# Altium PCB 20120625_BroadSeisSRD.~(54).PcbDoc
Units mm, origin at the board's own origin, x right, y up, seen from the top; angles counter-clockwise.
Board outline 68.5 x 51 mm, 4 copper layers (Top Layer, Mid-Layer 1, Mid-Layer 2, Bottom Layer); 59 components, 43 nets, 186 pads, 31 vias.
Unrouted connection lines stored in the file: 6.
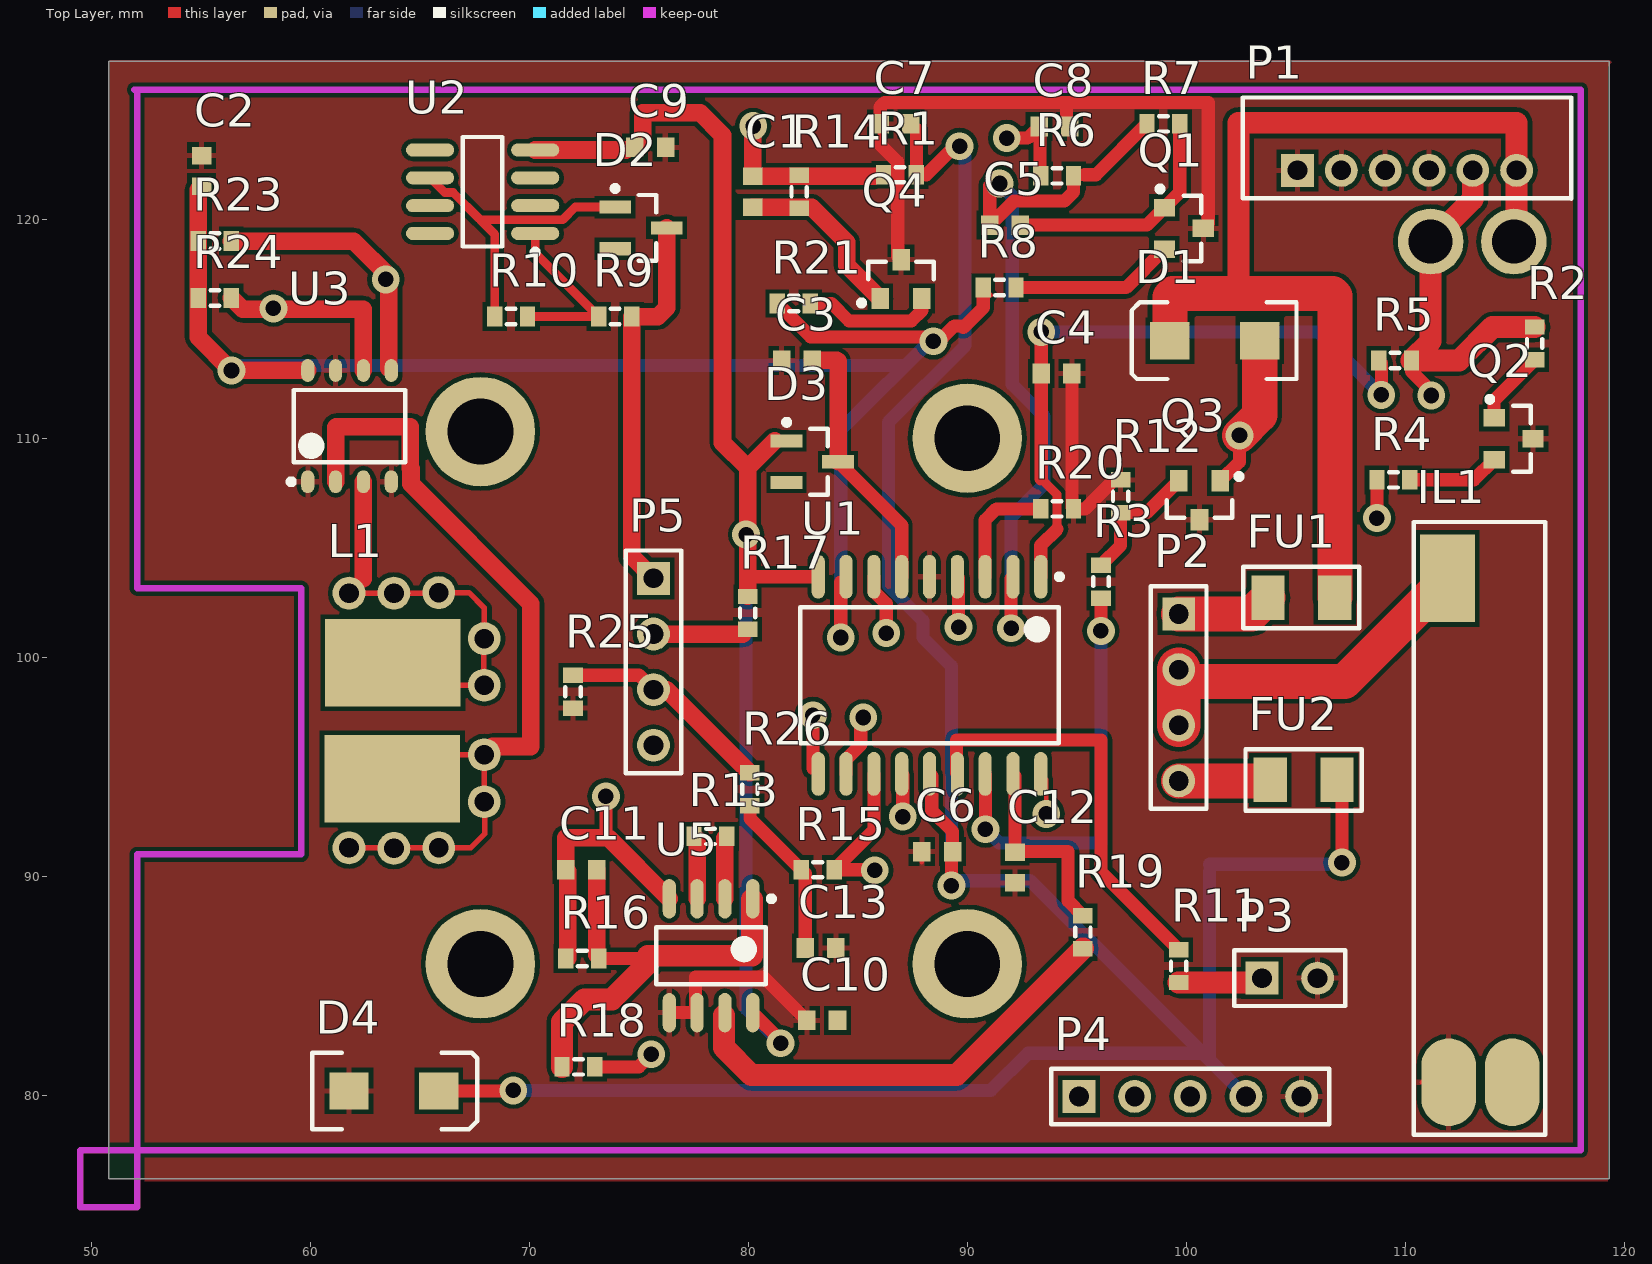
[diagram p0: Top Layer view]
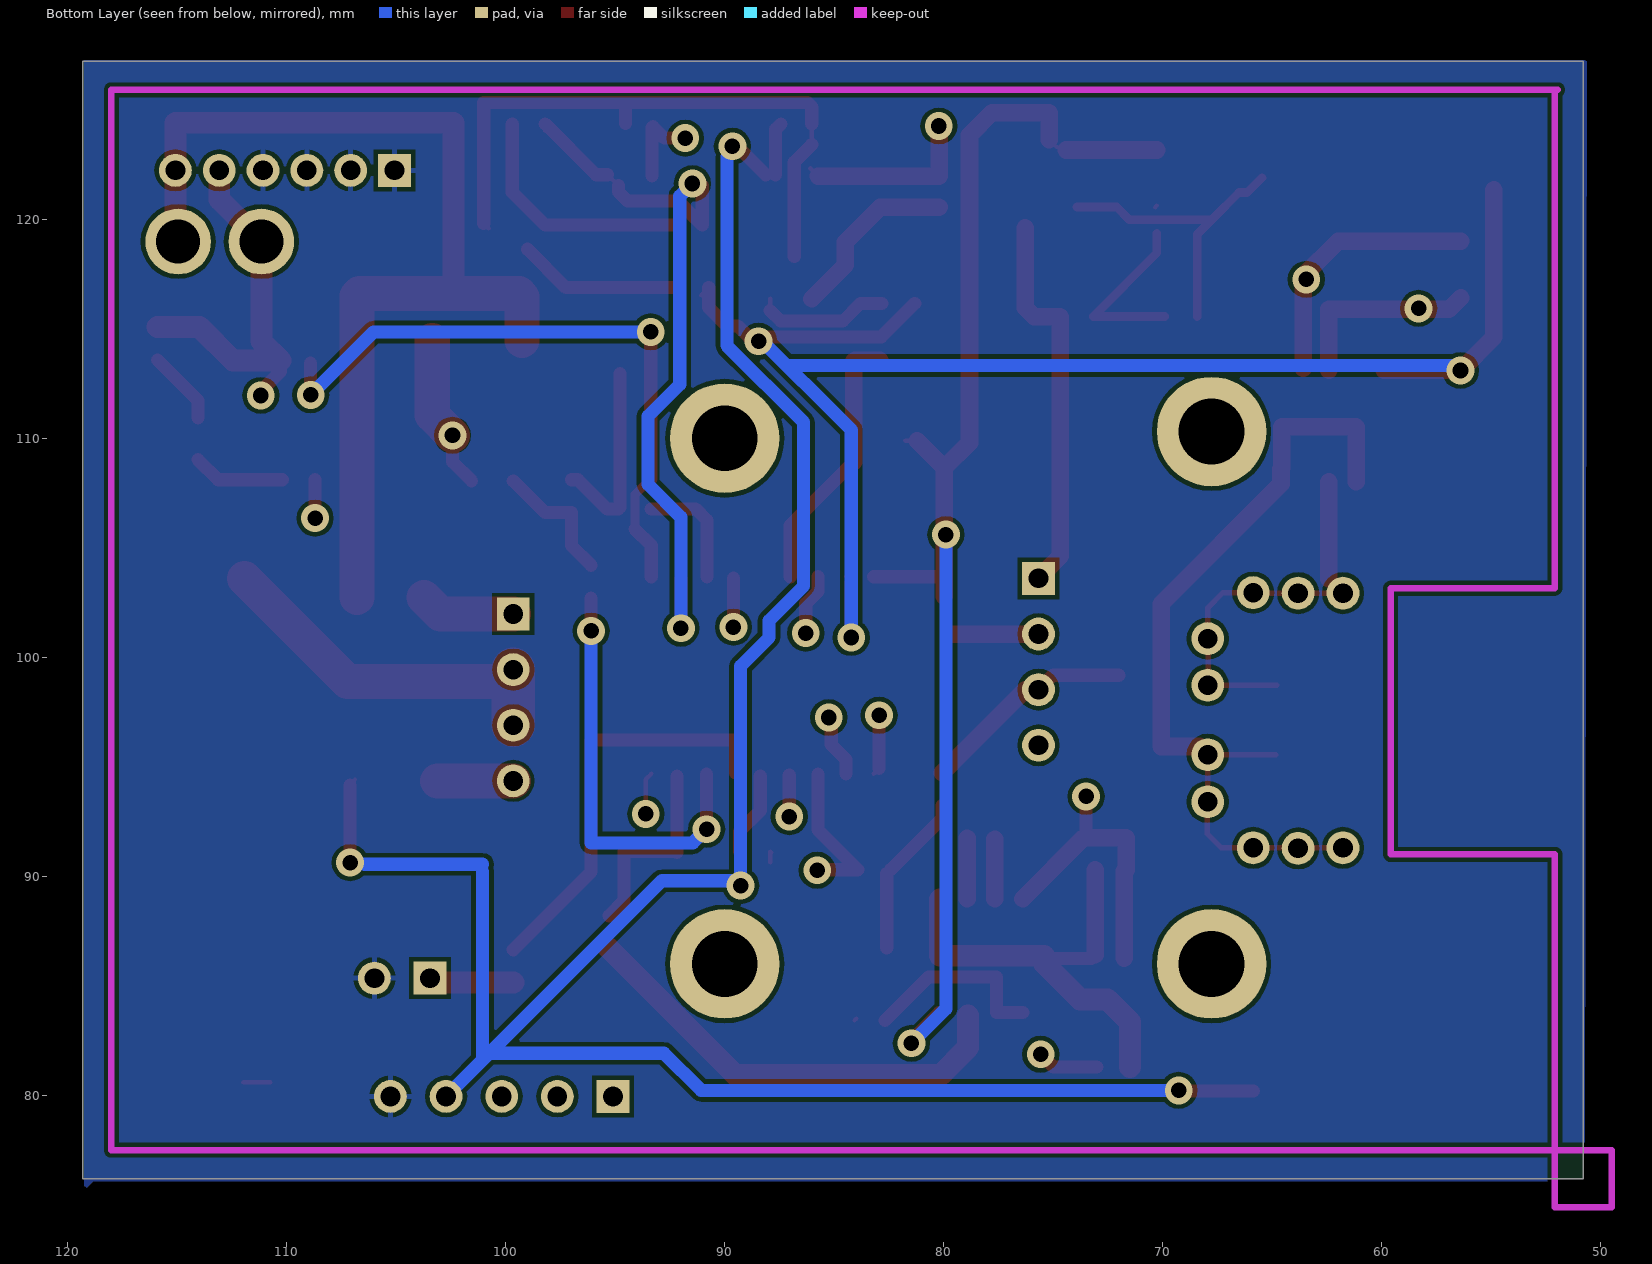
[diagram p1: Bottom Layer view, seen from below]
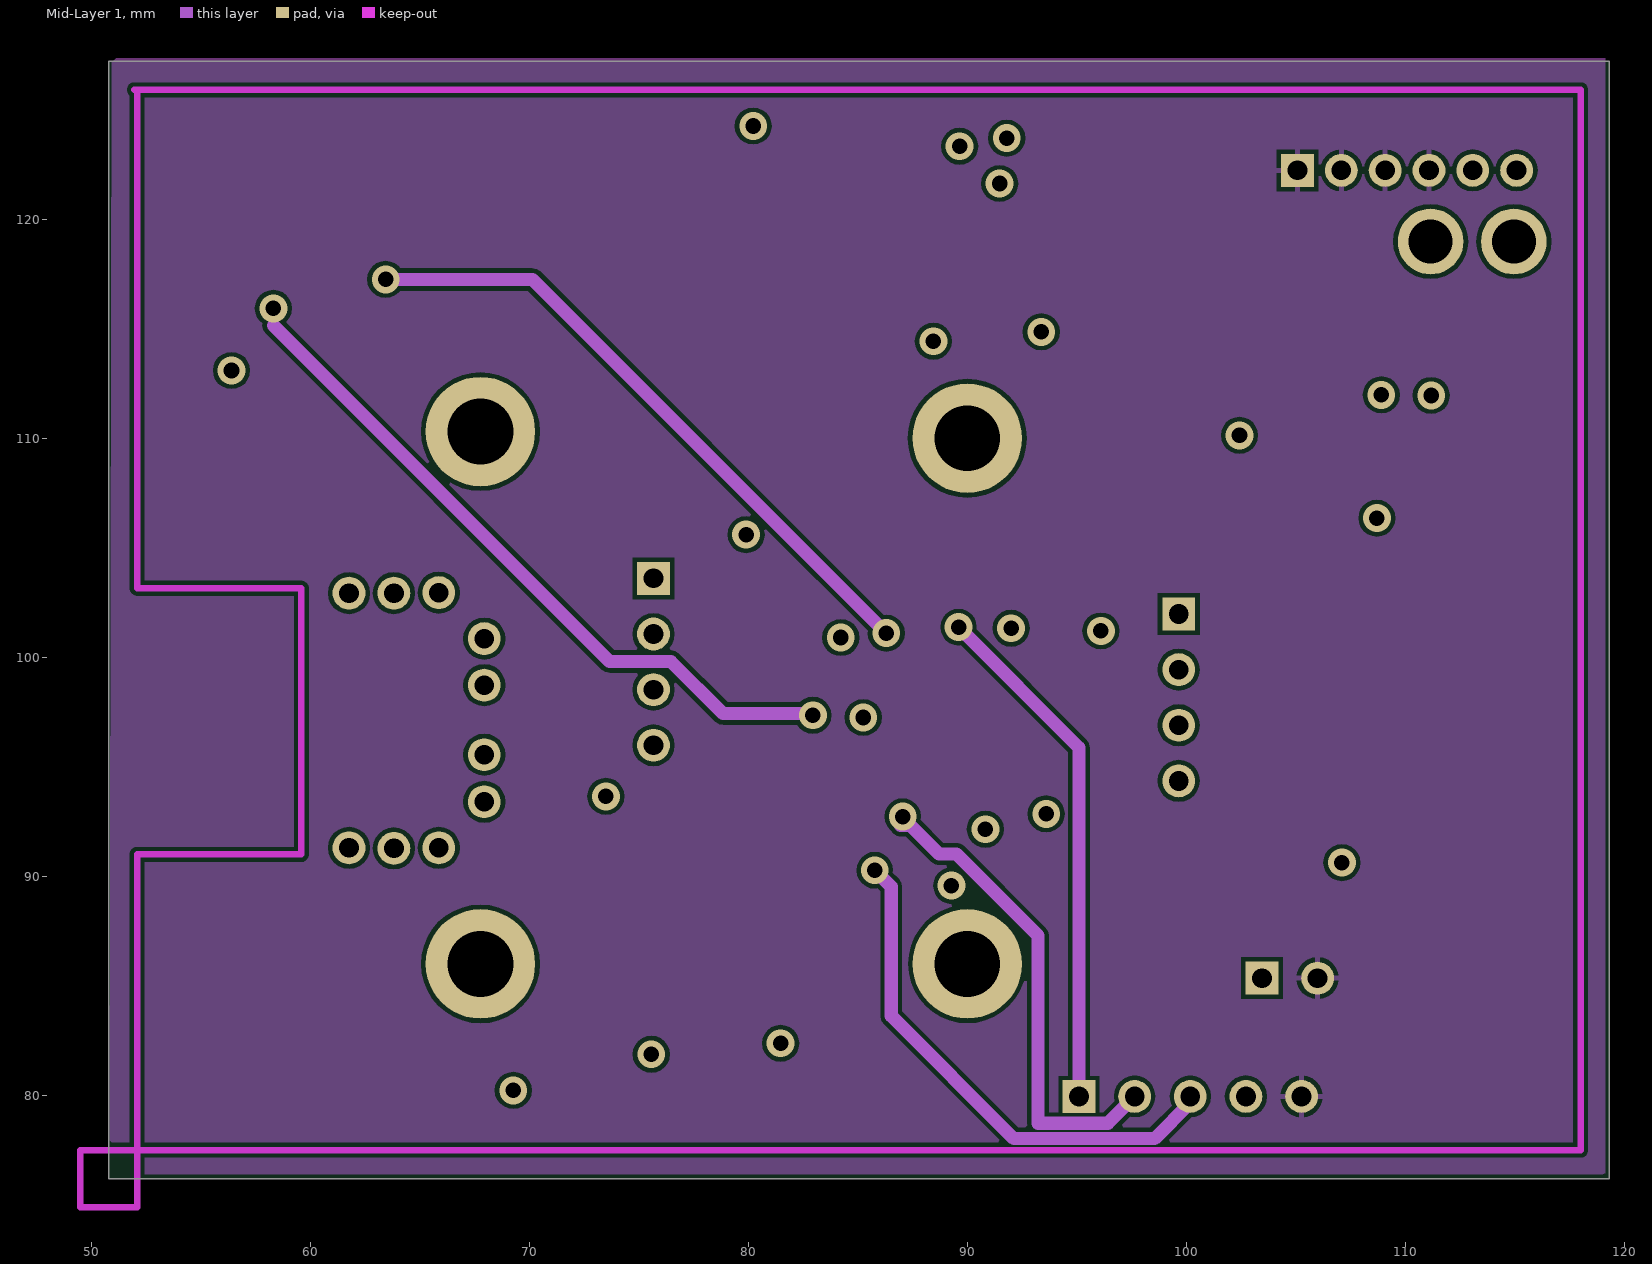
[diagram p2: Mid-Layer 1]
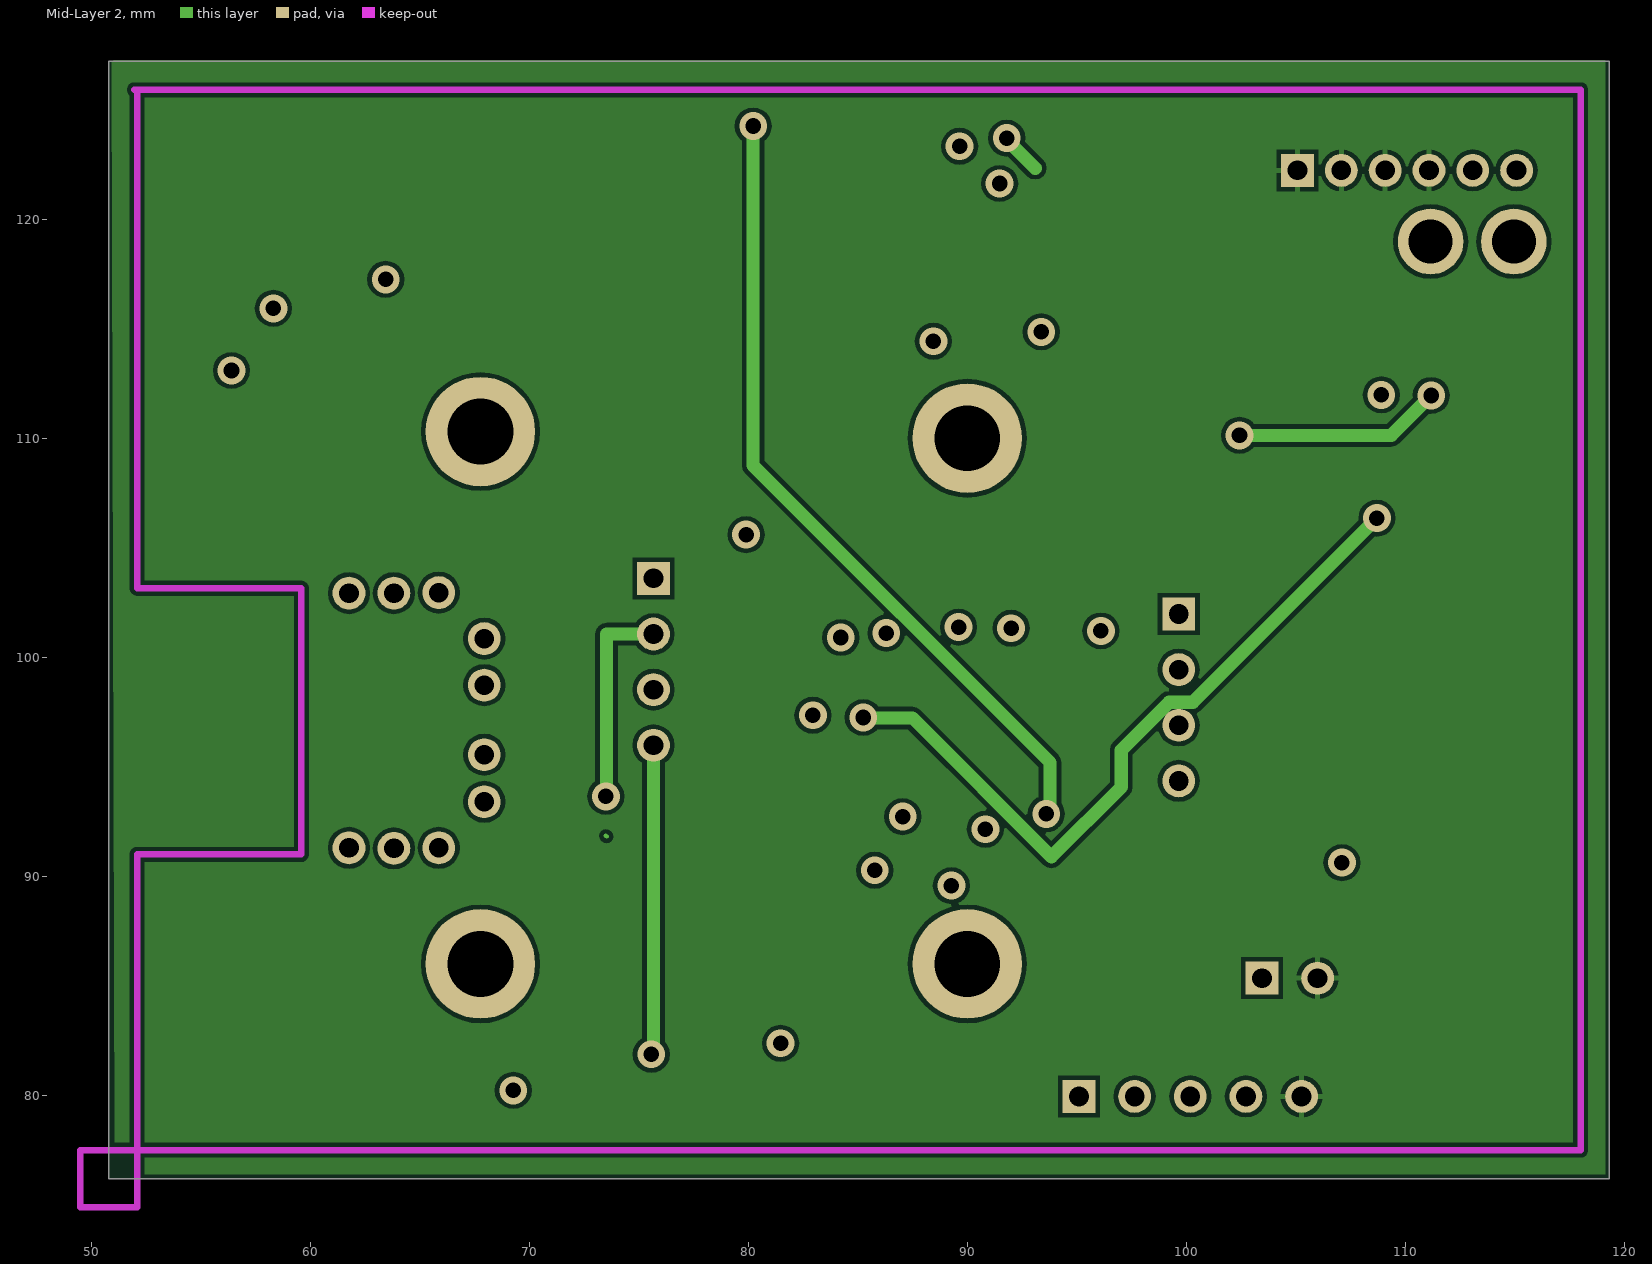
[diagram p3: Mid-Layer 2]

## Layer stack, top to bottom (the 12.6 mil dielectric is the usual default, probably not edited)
Top Layer: signal copper 0.0356
Dielectric: dielectric 0.32, FR-4, Dk 4.8
Mid-Layer 1: signal copper 0.0356
Dielectric: dielectric 0.32, FR-4, Dk 4.8
Mid-Layer 2: signal copper 0.0356
Dielectric: dielectric 0.32, FR-4, Dk 4.8
Bottom Layer: signal copper 0.0356

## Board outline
50.8,76.2 119.3,76.2 119.3,127.2 50.8,127.2

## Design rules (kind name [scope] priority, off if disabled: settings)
Clearance [All] p1: gap=0.2
PolygonConnect [All] p1: connectstyle=Relief reliefconductorwidth=0.254 reliefentries=4 polygonreliefangle="90 Angle"
RoomDefinition 2012_06_22_Sheet [InComponentClass('2012_06_22_Sheet')] p1: confinementstyle=ConfineIn formatcopy=TRUE lockcomponents=FALSE outline 124.968,76.183 450.469,76.183 450.469,107.298 124.968,107.298
RoutingVias [All] p1: holewidth=0.6 width=1 viastyle="Through Hole" minholewidth=0.711 minwidth=1.27 maxholewidth=0.711 maxwidth=1.27
SilkscreenOverComponentPads [All] p1: minsilkscreentomaskgap=0.254
SolderMaskExpansion [All] p1: expansion=0.102
Width [All] p1: maxlimit=0.2 minlimit=0.2 preferedwidth=0.2
27 further rules are at their usual default settings.

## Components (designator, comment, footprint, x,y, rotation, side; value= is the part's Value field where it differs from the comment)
C1 "Cap Semi" 1608[0603] 80.2,121.25 r90 top
C2 "Cap Semi" 1608[0603] 55.05,122.2 r270 top
C3 "Cap Semi" 1608[0603] 82.225,113.55 r0 top
C4 "Cap Semi" 1608[0603] 94.075,112.95 r180 top
C5 "Cap Semi" 1608[0603] 91.725,119.725 r180 top
C6 "Cap Semi" 1608[0603] 88.625,91.125 r0 top
C7 "Cap Semi" 1608[0603] 86.725,124.35 r0 top
C8 "Cap Semi" 1608[0603] 93.975,124.225 r180 top
C9 "Cap Semi" 1608[0603] 75.525,123.275 r180 top
C10 "Cap Semi" 1608[0603] 83.375,83.425 r0 top
C11 "Cap Semi" 1608[0603] 72.375,90.3 r180 top
C12 "Cap Semi" 1608[0603] 92.175,90.4 r90 top
C13 "Cap Semi" 1608[0603] 83.3,86.725 r180 top
D1 "RS1D" DiodeRS1D(recommendedfootprint) 101.3,114.45 r180 top
D2 "Diode BAS16" SOT-23_M 75.1,119.6 r0 top
D3 "Diode BAS16" SOT-23_M 82.925,108.925 r0 top
D4 "RS1D" DiodeRS1D(recommendedfootprint) 63.825,80.2 r0 top
FU1 "1A" FU(recommendedfootprint) 105.25,102.725 r0 top
FU2 "200mA" FU(recommendedfootprint) 105.35,94.4 r180 top
IL1 "ILS" ILS 114.875,103.6 r270 top
L1 "Inductor" INDC4532 63.775,97.1 r270 top
P1 "ConnectorToFB" "HIROSE DF3A-6P" 105.075,122.225 r0 top
P2 "Battery Pack pigtail" HDR1X4 99.65,101.975 r270 top
P3 "Connector to LED" HDR1X2 103.45,85.35 r0 top
P4 "Connector to Prog." HDR1X5 95.1,79.95 r0 top
P5 "Pressure Transducer pigtail" HDR1X4 75.675,103.6 r270 top
Q1 "NPN" transistor_SOT-23(recommendedfootprint) 99.975,119.575 r0 top
Q2 "NPN" transistor_SOT-23(recommendedfootprint) 115.025,109.975 r0 top
Q3 "MOSFET-IRLML" transistor_SOT-23(recommendedfootprint) 100.6,107.075 r270 top
Q4 "NPN" transistor_SOT-23(recommendedfootprint) 86.975,117.35 r90 top
R1 "Res3" J1-0603 86.925,122.025 r0 top
R2 "Res3" J1-0603 115.9,114.325 r90 top
R3 "Res3" J1-0603 96.1,103.45 r90 top
R4 "Res3" J1-0603 109.45,108.1 r0 top
R5 "Res3" J1-0603 109.525,113.55 r0 top
R6 "Res3" J1-0603 94.1,121.975 r180 top
R7 "Res3" J1-0603 98.95,124.35 r180 top
R8 "Res3" J1-0603 91.475,116.875 r0 top
R9 "Res3" J1-0603 73.925,115.55 r0 top
R10 "Res3" J1-0603 69.175,115.55 r180 top
R11 "Res3" J1-0603 99.65,85.9 r90 top
R12 "Res3" J1-0603 97,107.35 r270 top
R13 "Res3" J1-0603 78.275,91.825 r0 top
R14 "Res3" J1-0603 82.325,121.25 r90 top
R15 "Res3" J1-0603 83.175,90.3 r180 top
R16 "Res3" J1-0603 72.425,86.25 r180 top
R17 "Res3" J1-0603 79.975,102.025 r90 top
R18 "Res3" J1-0603 72.25,81.3 r180 top
R19 "Res3" J1-0603 95.275,87.45 r90 top
R20 "Res3" J1-0603 94.1,106.775 r180 top
R21 "Res3" J1-0603 82.075,116.15 r0 top
R23 "Res3" J1-0603 55.65,119 r0 top
R24 "Res3" J1-0603 55.65,116.4 r180 top
R25 "Res3" J1-0603 72,98.425 r90 top
R26 "Res3" J1-0603 80.075,93.975 r90 top
U1 "PIC16LF1827-I/SO" SOIC-SO18_L 88.275,99.175 r270 top
U2 "LM334D" SO8_N 67.875,121.25 r180 top
U3 "M24LR64" SO8N_N 61.8,110.55 r90 top
U5 "AD620BR" R-8D_N 78.3,86.375 r270 top

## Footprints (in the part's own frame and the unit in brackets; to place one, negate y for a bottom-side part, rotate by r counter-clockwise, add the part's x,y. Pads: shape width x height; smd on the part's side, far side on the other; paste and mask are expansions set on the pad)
1608[0603] [mm] "Chip Capacitor, Body 1.6x0.8mm, IPC High Density"
  rect 0.8x0.9 smd: 1(-0.7,0) 2(0.7,0)
  body extent -0.87,-0.48 0.87,0.48, height 1.3
DiodeRS1D(recommendedfootprint) [mm] "DO-214-AB/SMC; 2 C-Bend Leads; Body 7.9 x 5.9 mm, inc. leads (LxW)"
  rect 1.8x1.7 smd: 1(-2.05,0) 2(2.05,0)
  silkscreen extent -3.73,-1.75 3.8,1.75
FU(recommendedfootprint) [mm] "Thru-Hole; 2 Leads"
  rect 1.52x2.03 smd: 1(-1.525,0) 2(1.525,0)
  silkscreen extent -2.65,-1.4 2.65,1.4
HDR1X2 [mm] "Connector; Header; 2 Position"
  rect 1.5x1.5 hole 0.9: 1(0,0)
  round 1.5 hole 0.9: 2(2.54,0)
  silkscreen extent -1.27,-1.27 3.81,1.27
HDR1X4 [mm] "Connector; Header; 4 Position"
  rect 1.5x1.5 hole 0.9: 1(0,0)
  round 1.5 hole 0.9: 2(2.54,0) 3(5.08,0) 4(7.62,0)
  silkscreen extent -1.27,-1.27 8.89,1.27
HDR1X5 [mm] "Connector; Header; 5 Position"
  rect 1.5x1.5 hole 0.9: 1(0,0)
  round 1.5 hole 0.9: 2(2.54,0) 3(5.08,0) 4(7.62,0) 5(10.16,0)
  silkscreen extent -1.27,-1.27 11.43,1.27
"HIROSE DF3A-6P" [mm] "Connector; Header; 6 Position"
  rect 1.5x1.5 hole 0.9: 1(0,0)
  round 1.5 hole 0.9: 2(2,0) 3(4,0) 4(6,0) 5(8,0) 6(10,0)
  round 3 hole 2: 5(6.075,-3.25) 6(9.875,-3.25)
  Top Layer lines w0.254: 9.875,-3.25 10,-2.75
  Top Layer lines w1: 6.075,-3.25 8,-1.325 8,0 ; 10,-2.75 10,0
  silkscreen extent -2.5,-1.29 12.5,3.32
ILS [mm]
  rect 4x2.5 smd: 1(0,-2.95)
  oval 4x2.5 smd: 2(23,-2.9) 3(23,0)
  silkscreen extent -2.58,-4.5 25.4,1.5
INDC4532 [mm] "Chip Inductor, Body 4.5x3.2mm, IPC High Density"
  round 1.5 hole 0.9: 1(-5.85,2.1) 1(-5.825,0.05) 1(-5.825,-2) 1(-3.75,4.175) 1(-1.625,4.175) 2(1.55,4.175) 2(3.7,4.175) 2(5.8,2.1) 2(5.8,-2) 2(5.825,0.05)
  rect 4x6.2 smd: 1(-2.65,0) 2(2.65,-0.025)
  Top Layer lines w0.254: -5.825,-2 -5.825,0.05 -5.825,2.075 -5.85,2.1 -5.85,3.475 -5.15,4.175 -3.75,4.175 -3.725,4.15 ; 1.55,1.075 1.55,4.175 3.7,4.175 3.725,4.2 5.15,4.2 5.8,3.55 5.8,2.1 5.8,0.075 ; -1.625,4.175 -1.625,4.15 ; 5.8,0.05 5.8,-2 5.8,0.05 ; 5.8,0.05 5.8,0.075 ; 5.8,0.05 5.8,0.075 ; -1.625,1.068 -1.625,4.15 ; -1.625,1.068 -1.625,1.025 -1.625,1.068 ; -1.625,1.068 -1.625,4.15 ; -1.625,4.15 -3.725,4.15 ; -1.625,4.15 -3.725,4.15
J1-0603 [mm] "Chip Resistor, Body 1.6x0.8mm, IPC High Density"
  rect 0.7x0.9 smd: 1(-0.75,0) 2(0.75,0)
  silkscreen extent -0.2,-0.35 0.2,0.35, body extent -0.85,-0.48 0.85,0.48, height 0.9
R-8D_N [mm] "SOIC, 8-Leads, Body 4.9x3.9mm, Pitch 1.27mm, IPC Medium Density"
  oval 1.8x0.6 smd: 1(-2.6,1.905) 2(-2.6,0.635) 3(-2.6,-0.635) 4(-2.6,-1.905) 5(2.6,-1.905) 6(2.6,-0.635) 7(2.6,0.635) 8(2.6,1.905)
  silkscreen extent -2.72,-2.5 1.3,2.88, body extent -2,-2.5 2,2.5, height 2.59
SO8_N [mm] "SOIC, 8-Leads, Body 4.9x3.9mm, Pitch 1.27mm, IPC Medium Density"
  oval 2.2x0.6 smd: 1(-2.4,1.905) 2(-2.4,0.635) 3(-2.4,-0.635) 4(-2.4,-1.905) 5(2.4,-1.905) 6(2.4,-0.635) 7(2.4,0.635) 8(2.4,1.905)
  silkscreen extent -2.53,-2.5 0.9,2.88, body extent -1.95,-2.45 1.95,2.45, height 1.75
SO8N_N [mm] "SOP, 8-Leads, Body 5.3x5.3mm, Pitch 1.27mm, IPC Medium Density"
  oval 1.04x0.6 smd: 1(-2.54,1.905) 2(-2.54,0.635) 3(-2.54,-0.635) 4(-2.54,-1.905) 5(2.54,-1.905) 6(2.54,-0.635) 7(2.54,0.635) 8(2.54,1.905)
  silkscreen extent -2.66,-2.54 1.65,2.79, body extent -2.29,-2.54 2.29,2.54, height 2.13
SOIC-SO18_L [mm] "SOIC, 18-Leads, Body 11.5x7.5mm, Pitch 1.27mm, IPC High Density"
  oval 2x0.6 smd: 1(-4.5,5.08) 2(-4.5,3.81) 3(-4.5,2.54) 4(-4.5,1.27) 5(-4.5,0) 6(-4.5,-1.27) 7(-4.5,-2.54) 8(-4.5,-3.81) 9(-4.5,-5.08) 10(4.5,-5.08) 11(4.5,-3.81) 12(4.5,-2.54) 13(4.5,-1.27) 14(4.5,0) 15(4.5,1.27) 16(4.5,2.54) 17(4.5,3.81) 18(4.5,5.08)
  silkscreen extent -4.62,-5.9 3.1,6.06, body extent -3.8,-5.95 3.8,5.95, height 2.65
SOT-23_M [mm] "SOT23, 3-Leads, Body 2.9x1.3mm, Pitch 0.95mm, Lead Span 2.5mm, IPC Low Density"
  rect 1.45x0.6 smd: 1(-1.175,0.95) 2(-1.175,-0.95) 3(1.175,0)
  silkscreen extent -1.3,-1.5 0.7,1.92, body extent -0.7,-1.5 0.7,1.5, height 1.1
transistor_SOT-23(recommendedfootprint) [mm] "SOT23, 3-Leads, Body 2.9x1.3mm, Pitch 0.95mm, Lead Span 2.5mm, IPC Low Density"
  rect 0.972x0.802 smd: 1(-0.975,0.95) 2(-0.975,-0.95) 3(0.8,0)
  silkscreen extent -1.3,-1.5 0.7,1.92, body extent -0.7,-1.5 0.7,1.5, height 1.1

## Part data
C1 C2 C3 C4 C5 C6 C7 C8 C9 C10 C11 C12 C13: "Capacitor (Semiconductor SIM Model)"
D1 D4: library part Diode, "Default Diode"
D2 D3: "Silicon Switching Diode for High-Speed Switching"
FU1 FU2: library part "Fuse 1", "Fuse"
IL1: "SPDT Subminiature Toggle Switch, Right Angle Mounting, Vertical Actuation"
P1: "Header, 6-Pin"
P2 P5: "Header, 4-Pin"
P3: "Header, 2-Pin"
P4: "Header, 5-Pin"
Q1 Q2 Q4: "NPN Bipolar Transistor"
Q3: "N-Channel MOSFET"
R1 R2 R3 R4 R5 R6 R7 R8 R9 R10 R11 R12 R13 R14 R15 R16 R17 R18 R19 R20 R21 R23 R24 R25 R26: "Resistor"
U1: "EPROM-Based 8-Bit CMOS Microcontroller, 25 Bytes RAM, 4 MHz, 18-Pin SOIC, 3.0 to 5.5V Supply Range, Extended Temperature"
U2: "Three Terminal Adjustable Current Source"
U3: "32 Kbit Serial I²C Bus EEPROM"
U5: "Low-Cost, Low-Power Instrumentation Amplifier"

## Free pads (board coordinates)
  round 5 hole 3: 1(67.775,86) 1(67.775,110.3) 1(90,86) 1(90,110)

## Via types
v1: diameter 1.27, hole 0.711, Top Layer to Bottom Layer, 31 vias

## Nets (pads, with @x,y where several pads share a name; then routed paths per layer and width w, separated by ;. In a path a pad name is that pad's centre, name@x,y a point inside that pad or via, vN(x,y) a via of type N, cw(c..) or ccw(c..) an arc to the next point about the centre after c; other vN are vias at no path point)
ACTIVATION+: FU1.1 P2.1 | length 4.4
  Top Layer w1.6: P2.1 102.975,101.975 FU1.1
ANA_PRESSURE: C12.2 R19.2 U1.17 | length 9.3
  Top Layer w0.2: U1.17 U1.17@92.175,94.585 ; C12.2 C12.2@92.2,91.125
  Top Layer w0.6: C12.2 U1.17@92.175,94.585 ; C12.2@92.2,91.125 94.6,91.125 94.6,88.875 R19.2
B7: P4.2 U1.13 | length 23.8
  Top Layer w0.2: U1.13 U1.13@87.05,94.63
  Top Layer w0.6: v1(87.05,92.725) U1.13@87.05,94.63
  Mid-Layer 1 w0.6: v1@86.95,92.325 87.4,92.325 88.7,91.025 89.5,91.025 93.225,87.3 93.225,78.725 96.415,78.725 P4.2
CHECK-FIRE: R4.1 U1.11 | length 38
  Top Layer w0.2: v1@85.135,97.135 v1(85.25,97.25)
  Top Layer w0.6: U1.11 84.465,95.34 85.135,96.01 v1@85.135,97.135 ; v1(108.7,106.35) R4.1
  Mid-Layer 2 w0.6: v1@85.325,97.225 87.5,97.225 93.838,90.887 97.025,94.075 97.025,95.755 99.215,97.945 100.295,97.945 v1(108.7,106.35)
FB1: C8.2 D1.2 FU1.2 P1.6 R6.2 | length 52.1
  Top Layer w0.2: C8.2 C8.2@93.325,124.175 ; 99.25,116.45 99.4,116.6 ; 102.325,116.6 102.375,116.65 ; 106.675,116.6 106.775,116.5
  Top Layer w0.6: v1(91.8,123.7) 92.75,123.7 C8.2 ; R6.2@93.325,121.975 C8.2@93.325,124.175
  Top Layer w1: 102.375,116.65 102.375,124.4 115.075,124.4 P1.6@115.075,122.225
  Top Layer w1.6: D1.2 99.25,116.45 ; 99.4,116.6 102.325,116.6 106.675,116.6 ; FU1.2 106.775,116.5
  Mid-Layer 2 w0.6: v1@91.65,123.775 93.1,122.325
FB2: D1.1 P1.5 Q3.1 R2.2 R5.2 | length 30.5
  Top Layer w0.6: Q3.1 102.425,108.925 v1(102.425,110.125) ; R5.2 110.275,113.05 v1@111.175,112.15
  Top Layer w1: P1.5@111.15,118.975 111.15,114.425 R5.2 112.45,113.55 113.975,115.075 R2.2
  Top Layer w1.6: v1(102.425,110.125) 103.35,111.05 D1.1
  Mid-Layer 2 w0.6: v1(102.425,110.125) 109.35,110.125 v1(111.175,111.95)
FIRE: R3.1 U1.16 | length 19.2
  Top Layer w0.2: U1.16 U1.16@90.825,94.665
  Top Layer w0.6: v1(90.825,92.15) U1.16@90.825,94.665 ; v1(96.1,101.2) R3.1
  Bottom Layer w0.6: v1(90.825,92.15) 91.45,91.525 96.1,91.525 v1(96.1,101.2)
FLASH_LED: R11.2 U1.15 | length 19.2
  Top Layer w0.2: U1.15@89.5,94.72 U1.15
  Top Layer w0.6: U1.15@89.5,94.72 89.5,96.225 96.1,96.225 96.1,90.2 R11.2
GND: C2.1 C3.1 C4.1 C6.1 C7.1 C8.1 C9.1 C10.1 C12.1 C13.1 D4.1 IL1.2 P1.1 P1.2 P1.3 P1.4 P3.2 P4.5 Q1.3 Q2.3 Q3.3 Q4.3 R12.1 R20.1 R25.1 U1.5 U3.1 U3.4 U3.7 U5.5 U5.6 | length 49
  Top Layer w0.2: U5.6@77.6,83.775 77.6,83.84 U5.6 ; 84,83.5 84.075,83.425 ; 86.025,123.399 C7.1 ; C6.1@87.875,91.075 C6.1 87.925,90.65 ; C12.1@92.075,89.8 C12.1 ; C8.1@94.525,124.375 C8.1 ; R20.1@94.775,106.85 R20.1 ; Q1.3 Q1.3@101,119.8 ; IL1.2@110.74,80.6 IL1.2
  Top Layer w0.6: U5.5 U5.6@77.6,83.775 ; U5.6@77.6,83.84 77.6,85.4 80.7,85.4 C10.1 ; 86.025,123.399 86.825,122.599 Q4.3@86.825,118.3 ; C7.1 86.025,125.125 86.225,125.325 94.525,125.325 ; C8.1@94.525,124.375 94.525,125.325 ; R20.1@94.775,106.85 C4.1 ; R20.1 95.375,106.775 96.7,108.1 R12.1 ; Q1.3@101,119.8 101,125.325 94.525,125.325
IN+: D2.3 P4.3 P5.1 R9.2 R15.1 U1.12 | length 48.7
  Top Layer w0.2: v1@85.75,90.3 v1(85.775,90.275)
  Top Layer w0.6: U1.12 85.735,92.11 R15.1 v1@85.75,90.3
  Top Layer w0.8: P5.1 74.675,104.6 R9.2 75.875,115.55 76.275,115.95 D2.3
  Mid-Layer 1 w0.2: P4.3@100.18,79.655 P4.3
  Mid-Layer 1 w0.6: v1(85.775,90.275) 86.525,89.525 86.525,83.625 92.125,78.025 98.55,78.025 P4.3@100.18,79.655
IN-: P5.3 R25.2 R26.2 | length 9.3
  Top Layer w0.6: R25.2 75.02,99.175 P5.3
  Top Layer w0.8: P5.3@76.28,98.52 R26.2
LED+: P3.1 R11.1 | length 3.6
  Top Layer w1: R11.1 P3.1@103.25,85.15
LP0-VDD: C2.2 R8.1 R21.1 R23.1 R24.2 U1.8 U3.8 | length 74
  Top Layer w0.2: C2.2@54.9,121.35 C2.2 ; U1.8@84.225,103.435 U1.8 ; R8.1 R8.1@91.075,116.525
  Top Layer w0.6: R21.1 82.85,114.625 88.909,114.625 89.409,115.125 89.741,115.125 89.816,115.05 90.725,115.959 R8.1 ; v1(84.225,100.9) U1.8@84.225,103.435
  Top Layer w0.8: C2.2@54.9,121.35 R23.1 R24.2 54.9,114.6 v1(56.41,113.09) U3.8
  Bottom Layer w0.2: v1(56.41,113.09) v1@56.645,113.325
  Bottom Layer w0.6: v1@56.645,113.325 87.175,113.325 ; v1(84.225,100.9) 84.225,110.375 v1@88.575,114.725
  other v1: 88.45,114.425
LP1-VDD: C9.2 D3.1 R17.2 U1.9 U2.4 U5.8 | length 63.1
  Top Layer w0.2: C9.2 C9.2@75.175,123.625 ; 79.975,103.725 80.025,103.675 ; D3.1@81.2,109.875 D3.1 ; v1(81.475,82.375) v1@81.475,82.505
  Top Layer w0.6: 80.025,103.675 U1.9 ; U5.8 v1@81.475,82.505
  Top Layer w0.8: U2.4 74.405,123.155 ; C9.2@75.175,123.625 75.175,124.85 77.8,124.85 78.825,123.825 78.825,109.8 79.975,108.65 ; R17.2 79.975,103.725 79.975,108.65 ; D3.1@81.2,109.875 79.975,108.65
  Bottom Layer w0.2: v1(81.475,82.375) v1@81.7,82.15
  Bottom Layer w0.6: v1(79.9,105.6) 79.9,83.95 v1(81.475,82.375)
LP1_VDD: C10.2
MCLR/: P4.1 U1.4 | length 26
  Top Layer w0.2: U1.4 U1.4@89.6,103.62
  Top Layer w0.6: v1(89.6,101.375) U1.4@89.6,103.62
  Mid-Layer 1 w0.6: v1(89.6,101.375) 95.1,95.875 P4.1
NetC1_1: C1.1 Q4.1 R14.1 | length 8.2
  Top Layer w0.8: C1.1 82.9,120.55 84.5,118.95 84.5,117.9 Q4.1
NetC3_2: C3.2 D3.3 R20.2 U1.3 U1.6 | length 17.6
  Top Layer w0.2: 84.05,113.55 84.1,113.5
  Top Layer w0.6: D3.3 87.005,106.02 U1.6 ; U1.3 90.815,106.265 91.325,106.775 R20.2
  Top Layer w0.8: C3.2 84.05,113.55 ; D3.3 84.1,113.5
NetC5_1: C5.1 Q1.1 R7.1 | length 11
  Top Layer w0.6: C5.1 98.2,119.725 Q1.1 99.7,121.225 R7.1
NetC11_1: C11.1 R16.1 R18.2 U5.1 | length 20.8
  Top Layer w0.2: R16.1@73.075,86.425 73.25,86.25 R16.1 ; 75.3,86.25 75.425,86.375
  Top Layer w0.6: R16.1@73.25,86.25 75.3,86.25
  Top Layer w0.8: R16.1@73.075,86.425 C11.1
  Top Layer w1: R18.2 71.5,83.35 72.525,84.375 73.775,84.375 75.425,86.025 ; 75.425,86.375 80.175,86.375 U5.1@80.175,88.945
NetC13_2: C13.2 R15.2 R26.1 | length 7.5
  Top Layer w0.2: R15.2 R15.2@82.6,90.125
  Top Layer w0.6: R26.1 80.075,92.65 R15.2 ; C13.2 R15.2@82.6,90.125
NetD2_1: D2.1 R10.2 U2.6 | length 14.2
  Top Layer w0.2: 70.275,120.615 70.34,120.55
  Top Layer w0.4: U2.6 66.145,121.215 66.524,121.215 67.724,120.015 ; R10.2 68.425,119.314 67.764,119.975 71.525,119.975 72.1,120.55 D2.1
NetIL1_1: IL1.1 P2.2 P2.3 | length 17
  Top Layer w0.2: P2.2 100.185,98.9
  Top Layer w1.6: 100.185,98.9 107.225,98.9 IL1.1
  Top Layer w2: P2.3 P2.2
NetL1_1: L1.1 U3.3 | length 5.4
  Top Layer w0.2: L1.1@61.775,102.925 62.435,103.585
  Top Layer w0.8: 62.435,103.585 U3.3
NetL1_2: L1.2 U3.2 | length 25.1
  Top Layer w0.2: 61.165,110.49 61.2,110.525 ; L1.2@67.95,95.55 L1.2@68.325,95.925
  Top Layer w0.8: U3.2 61.165,110.49 ; 61.2,110.525 64.575,110.525 64.575,108.633 64.605,108.603 64.605,107.92 70.075,102.45 70.075,95.925 L1.2@68.325,95.925
NetQ1_2: Q1.2 R8.2 | length 7.5
  Top Layer w0.6: R8.2 97.25,116.875 Q1.2
NetQ2_1: Q2.1 R2.1 | length 3.4
  Top Layer w0.6: Q2.1 114.05,111.725 R2.1
NetQ2_2: Q2.2 R4.2 | length 4.2
  Top Layer w0.6: R4.2 113.125,108.1 Q2.2
NetQ3_2: Q3.2 R3.2 R12.2 | length 6
  Top Layer w0.6: R3.2 97,105.1 R12.2 98.2,106.6 Q3.2
NetQ4_2: Q4.2 R21.2 | length 6.2
  Top Layer w0.2: 87.925,115.825 Q4.2
  Top Layer w0.6: R21.2 83.8,116.15 84.6,115.35 87.45,115.35 87.925,115.825
NetR9_1: R9.1 R10.1 U2.1 | length 8.2
  Top Layer w0.4: R10.1 R9.1 70.275,118.45 U2.1
NetR13_1: R13.1 U5.3 | length 2.7
  Top Layer w0.8: U5.3 R13.1@77.665,91.685
NetR13_2: R13.2 U5.2 | length 2.8
  Top Layer w0.8: U5.2 R13.2@78.935,91.735
NetR19_1: R19.1 U5.7 | length 20.8
  Top Layer w1: U5.7@78.891,83.641 78.891,82.184 80.15,80.925 89.5,80.925 R19.1
OUT+: C11.2 P5.2 R16.2 R17.1 U5.4 | length 27
  Top Layer w0.2: C11.2 C11.2@71.75,90.225 ; 73.5,91.87 73.62,91.75
  Top Layer w0.6: 73.5,91.87 v1(73.5,93.65)
  Top Layer w0.8: C11.2 71.675,91.75 73.62,91.75 U5.4 ; R16.2@71.75,86.25 C11.2@71.75,90.225 ; P5.2 R17.1@79.76,101.06
  Mid-Layer 2 w0.2: 73.5,91.85 73.535,91.815 ; v1(73.5,93.65) v1@73.535,93.685
  Mid-Layer 2 w0.6: v1@73.535,93.685 73.535,101.06 P5.2
OUT-: P5.4 R18.1 | length 18
  Top Layer w0.2: v1(75.575,81.875) 75.875,81.875 v1@75.725,82.025
  Top Layer w0.6: R18.1 75,81.3 v1@75.725,82.025
  Mid-Layer 2 w0.2: v1(75.575,81.875) 75.875,81.875 v1@75.675,82.075
  Mid-Layer 2 w0.6: v1@75.675,82.075 P5.4
PCB+: FU2.2 P2.4 | length 3.5
  Top Layer w1.6: P2.4 FU2.2@103.12,94.355
SCLK: R24.1 U1.10 U3.6 | length 44.8
  Top Layer w0.2: U1.10@82.95,94.92 U1.10
  Top Layer w0.6: U1.10@82.95,94.92 v1(82.95,97.35)
  Top Layer w0.8: R24.1 56.915,115.885 62.435,115.885 U3.6
  Mid-Layer 1 w0.2: 58.325,115.15 v1(58.325,115.925)
  Mid-Layer 1 w0.6: 58.325,115.15 73.675,99.8 76.475,99.8 78.85,97.425 v1@83.15,97.425
SDA: R23.2 U1.7 U3.5 | length 44.1
  Top Layer w0.6: U1.7 85.735,103.015 86.3,102.45 v1(86.3,101.1)
  Top Layer w0.8: R23.2 62,119 63.6,117.4 U3.5@63.6,113.195
  Mid-Layer 1 w0.6: v1(63.45,117.25) 70.15,117.25 v1@86.05,101.35
VBAT1: C1.2 R1.1 R14.2 U1.18 | length 47.4
  Top Layer w0.2: 85.725,121.95 R1.1@86.1,122.325 ; U1.18 93.6,94.43 v1(93.6,92.85)
  Top Layer w0.8: v1@80.2,124.025 C1.2 85.725,121.95
  Mid-Layer 2 w0.6: v1(80.225,124.25) 80.225,108.75 93.775,95.2 v1@93.775,92.55
VBAT2: C5.2 R6.1 R7.2 U1.2 | length 36.2
  Top Layer w0.2: v1@91.025,121.525 90.95,121.6 90.975,121.625 v1(91.475,121.625) ; U1.2@92,103.59 U1.2 ; 94.85,121.525 95.35,122.025 ; R7.2@98.2,124.025 R7.2
  Top Layer w0.6: v1@91.025,121.525 C5.2 92.125,120.825 94.425,120.825 94.85,121.25 94.85,121.525 ; v1(92,101.325) U1.2@92,103.59 ; 95.35,122.025 95.875,122.025 R7.2
  Bottom Layer w0.6: v1(91.475,121.625) 92.05,121.05 92.05,112.45 93.5,111 93.5,107.9 92,106.4 v1(92,101.325)
VDD: C6.2 C7.2 D4.2 FU2.1 P4.4 R1.2 U1.14 | length 121.1
  Top Layer w0.2: v1@69.25,80.2 v1(69.275,80.225) ; R1.2 88.125,122.025 ; U1.14 U1.14@88.375,94.575 ; C6.2@89.275,91.075 C6.2 ; v1@89.425,123.325 v1(89.65,123.325) ; FU2.1 FU2.1@107.1,94.175
  Top Layer w0.6: D4.2 v1@69.25,80.2 ; C7.2 87.675,124.1 R1.2 ; 88.125,122.025 v1@89.425,123.325 ; U1.14@88.375,94.575 88.375,93 89.325,92.05 C6.2 ; v1(89.275,89.575) C6.2@89.275,91.075 ; v1(107.1,90.625) FU2.1@107.1,94.175
  Bottom Layer w0.2: v1(89.275,89.575) v1@89.275,89.8 ; v1(89.65,123.325) 89.425,123.325 v1@89.9,122.85 ; 100.745,81.925 P4.4
  Bottom Layer w0.6: v1(69.275,80.225) 91.075,80.225 92.775,81.925 100.745,81.925 ; v1@89.9,122.85 89.9,114.225 86.4,110.725 86.4,103.253 87.975,101.678 87.975,100.9 89.275,99.6 89.275,89.8 92.87,89.8 P4.4 ; 101.05,81.62 101.05,90.225 ; 101.05,90.55 106.45,90.55
VFIRE: C4.2 R5.1 U1.1 | length 30.1
  Top Layer w0.2: R5.1 R5.1@108.9,113.425
  Top Layer w0.4: 93.375,108.15 94.1,107.425 94.1,105.85
  Top Layer w0.6: U1.1 93.355,105.105 94.1,105.85 ; 93.375,108.15 C4.2 v1(93.375,114.85) ; v1(108.9,111.975) R5.1@108.9,113.425
  Bottom Layer w0.6: v1(93.375,114.85) 106.025,114.85 v1(108.9,111.975)
pads on no net: D2.2 D3.2 IL1.3 U2.2 U2.3 U2.5 U2.7 U2.8

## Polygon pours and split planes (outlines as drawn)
GND on Top Layer "Top Layer-No Net" (solid, pour order 4): 50.85,127.25 119.325,127.25 119.425,127.15 119.225,126.95 119.225,76.075 51.05,76.075 50.85,76.275
GND on Mid-Layer 1 "Top Layer-No Net" (solid, pour order 6): 50.95,127.15 51.15,127.35 119.125,127.35 119.125,76.275 119.225,76.175 119,76.4 50.85,76.4
GND on Mid-Layer 2 "Top Layer-No Net" (solid, pour order 8): 50.95,127.25 119.125,127.25 119.125,76.4 51.275,76.4 51.075,76.6
GND on Bottom Layer "Top Layer-No Net" (solid, pour order 10): 50.65,127.35 50.75,127.25 119.225,127.25 119.225,75.875 119.125,75.775 118.825,76.075 50.75,76.075

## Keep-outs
Keep-Out Layer:
  lines w0.3: 51.975,125.9 118,125.9 118,77.5 52.1,77.5 ; 52.1,125.9 52.1,120.213 52.1,108.837 52.1,103.15 59.6,103.15 59.6,97.1 59.6,91 52.1,91 52.1,77.5 ; 52.1,77.5 52.1,74.9 49.5,74.9 49.5,77.5 52.1,77.5

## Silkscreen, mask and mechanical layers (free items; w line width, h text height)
Drill Drawing:
  text ".LEGEND" at 128.952,79.739 h1.52
  text "Drill Drawing." at 128.952,77.199 h1.52

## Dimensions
50.8,76.2 to 52.1,77.5 on Mechanical 1
50.8,76.2 to 52.1,77.5 on Mechanical 1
